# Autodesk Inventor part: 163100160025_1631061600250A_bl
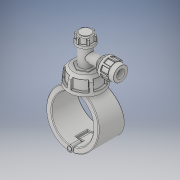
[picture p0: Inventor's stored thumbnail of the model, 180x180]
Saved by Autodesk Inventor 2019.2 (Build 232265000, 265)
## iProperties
Created: 2022-02
Part Number: 163100160025_1631061600250A_bl
Material: Generic
Description: Plassadle Tapper 125x25
Document SubType Name: Modeling
Designer: comp2
Density: 1 g/cm^3
Appearance: Default
Author: comp2
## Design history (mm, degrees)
derived "16310.ipt"
feature "Solid1::16310.ipt" dims "ScaleForDerivedMember" = 10
feature "Solid2::16310.ipt" dims "ScaleForDerivedMember" = 10
feature "Solid3::16310.ipt" dims "ScaleForDerivedMember" = 10
feature "Solid4::16310.ipt" dims "ScaleForDerivedMember" = 10
tag "TaggingFeature1"
body "Solid1"
body "Solid2"
body "Solid3"
body "Solid4"
other parameters: "d0" = 125 [user parameter], "d2" = 157 [user parameter], "d3" = 62.5 [user parameter], "d7" = 149.15 [user parameter], "d8" = 85 deg [user parameter], "d9" = 45 deg [user parameter], "d10" = 102 [user parameter], "d11" = 49 [user parameter], "d12" = 34.3 [user parameter], "d13" = 35.7 [user parameter], "d14" = 55.08 [user parameter], "d15" = 2.45 [user parameter], "d16" = 2 [user parameter], "d17" = 2 [user parameter], "d18" = 29.4 [user parameter], "d19" = 7.35 [user parameter], "d20" = 1 [user parameter], "d21" = 30.6 [user parameter], "d22" = 1 [user parameter], "d23" = 14.7 [user parameter], "d24" = 106 [user parameter], "d27" = 144 [user parameter], "d29" = 54 [user parameter], "d31" = 43.2 [user parameter], "d32" = 42.4 [user parameter], "d33" = 14.84 [user parameter], "d34" = 93 deg [user parameter], "d35" = 2 [user parameter], "d36" = 4 [user parameter], "d39" = 45 deg [user parameter], "d40" = 4 [user parameter], "d41" = 5 [user parameter], "d42" = 3.2 [user parameter], "d46" = 51 [user parameter], "d47" = 27 [user parameter], "d48" = 49 [user parameter], "d49" = 3.14 [user parameter], "d51" = 0 [user parameter], "d52" = 22.4 [user parameter], "d53" = 86.35 [user parameter], "d54" = 35 [user parameter], "d55" = 0 [user parameter], "d59" = 0 [user parameter], "d61" = 0 [user parameter], "d62" = 35 [user parameter], "d63" = 0 [user parameter], "d65" = 0 [user parameter], "d67" = 0 [user parameter], "d69" = 0 [user parameter], "d70" = 1 [user parameter], "d71" = 96 [user parameter], "d72" = 0 [user parameter], "d73" = 2 [user parameter], "d77" = 25 [user parameter], "d78" = 86.7 [user parameter], "d79" = 5.1 [user parameter], "d80" = 60 deg [user parameter], "d81" = 5.1 [user parameter], "d84" = 0 [user parameter], "d85" = 1 [user parameter], "d87" = 360 deg [user parameter], "d90" = 0 [user parameter], "d91" = 1 [user parameter], "d93" = 60 deg [user parameter], "d94" = 3.06 [user parameter], "d95" = 3.06 [user parameter], "d97" = 0 [user parameter], "d98" = 0.5 [user parameter], "d100" = 360 deg [user parameter], "d102" = 2 [user parameter], "d105" = 0 [user parameter], "d106" = 45 deg [user parameter], "d107" = 2.7 [user parameter], "d108" = 2.7 [user parameter], "d109" = 2.95332 [user parameter], "d110" = -8 [user parameter], "d112" = 0 [user parameter], "d113" = 0.5 [user parameter], "d115" = 360 deg [user parameter], "d117" = 0.5 [user parameter], "d" = 125 [user parameter], "d1" = 25 [user parameter], "B" = 157 [user parameter], "E_" = 54 [user parameter], "E1" = 102 [user parameter], "H2" = 144 [user parameter], "H3" = 106 [user parameter], "H_costum" = 49 [user parameter]
